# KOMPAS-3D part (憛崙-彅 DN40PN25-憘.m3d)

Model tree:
1. Объединить компоненты:1  (labels: СЕНС-ПФ DN40PN25)
2. Эскиз:1
3. Операция выдавливания:1
     Расстояние 1 = 14
4. Фаска:1
     Угол = 45; Длина 1 = 2; Длина 2 = 2

Referenced files in D:\Савин\!СЕНСОР\3D для заказчика\!Новый перечень\СЕНС-ПФ\DN40\: СЕНС-ПФ DN40PN25.a3d
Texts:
  СЕНС-ПФ DN40PN25-СВ
  ООО НПП Сенсор
  СЕНС-ПФ DN40PN25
